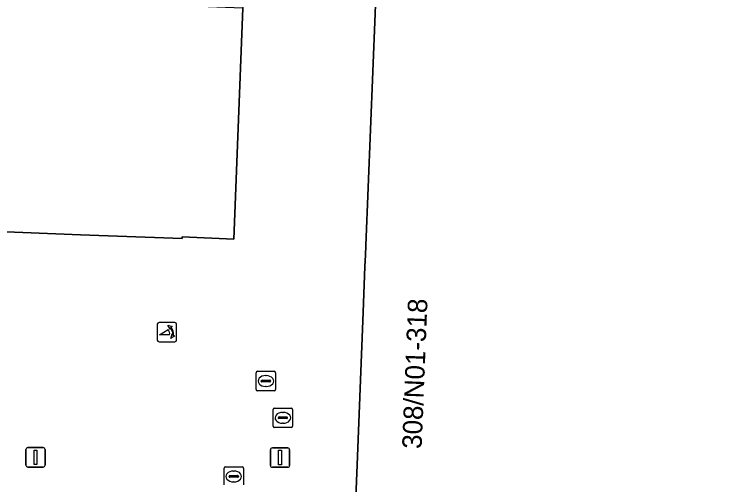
# Model space of a CAD drawing. Extents: x 160888 to 161385, y 386490 to 386908.
# Drawn here: x 161269.97 to 161306.64, y 386804.6 to 386828.79 of the extents above; entities that cross this region are included whole.
import ezdxf

# ---------------------------------------------------------------- set-up
doc = ezdxf.new("R2010")
doc.units = 0
for name, color, linetype in [('IMGEO_Kolk', 7, 'Continuous'), ('IMGEO_Lichtmast', 7, 'Continuous'), ('IMGEO_Pand', 7, 'Continuous'), ('IMGEO_Pand_nummerreeks', 7, 'Continuous'), ('IMGEO_Poller', 7, 'Continuous'), ('IMGEO_Rioolput', 7, 'Continuous'), ('IMGEO_Voetgangersgebied_open', 7, 'Continuous')]:
    doc.layers.add(name, color=color, linetype=linetype)

msp = doc.modelspace()

# ---------------------------------------------------------------- linework, layer by layer
at = {"layer": 'IMGEO_Kolk'}
for p, q in [((161280.752, 386804.599), (161280.752, 386805.451)), ((161280.827, 386805.525), (161281.679, 386805.525)), ((161281.753, 386805.451), (161281.753, 386804.599)), ((161281.054, 386805.068), (161281.452, 386805.068)), ((161281.24, 386805.305), (161281.265, 386805.305)), ((161281.011, 386805.019), (161281.011, 386805.031)), ((161281.449, 386804.982), (161281.051, 386804.982)), ((161281.263, 386804.745), (161281.238, 386804.745)), ((161281.495, 386805.031), (161281.495, 386805.019))]:
    msp.add_line(p, q, dxfattribs=at)
for points in [[(161280.752, 386804.599), (161280.752, 386805.451)], [(161280.827, 386805.525), (161281.679, 386805.525)], [(161281.753, 386805.451), (161281.753, 386804.599)]]:
    msp.add_lwpolyline(points, dxfattribs=at)
for centre, radius, start, end in [((161280.829, 386805.449), 0.0765, 91.552, 178.448), ((161280.829, 386805.449), 0.0765, 91.552, 178.448), ((161281.677, 386805.449), 0.0765, 1.552, 88.448), ((161281.677, 386805.449), 0.0765, 1.552, 88.448), ((161281.051, 386805.028), 0.0403, 85.8775, 175.7526), ((161281.456, 386805.03), 0.0386, 1.7309, 96.639), ((161281.048, 386805.018), 0.0366, 178.938, 274.7102), ((161281.452, 386805.025), 0.043, 264.8664, 352.4533)]:
    msp.add_arc(centre, radius, start, end, dxfattribs=at)
for centre, major_axis, ratio, start_param, end_param in [((161281.239, 386805.025), (-0.387, 0.002), 0.722429, 4.712389, 7.853982), ((161281.264, 386805.025), (-0.39, 0.002), 0.717154, 1.570796, 4.712389)]:
    msp.add_ellipse(centre, major_axis=major_axis, ratio=ratio, start_param=start_param, end_param=end_param, dxfattribs=at)
at = {"layer": 'IMGEO_Lichtmast'}
for p, q in [((161270.566, 386805.609), (161270.566, 386806.409)), ((161270.566, 386806.409), (161270.566, 386805.609)), ((161270.666, 386806.509), (161271.456, 386806.509)), ((161271.456, 386806.509), (161270.666, 386806.509)), ((161271.556, 386806.409), (161271.556, 386805.609)), ((161271.556, 386805.609), (161271.556, 386806.409)), ((161283.136, 386805.594), (161283.136, 386806.394)), ((161283.136, 386806.394), (161283.136, 386805.594)), ((161283.236, 386806.494), (161284.026, 386806.494)), ((161284.026, 386806.494), (161283.236, 386806.494)), ((161284.126, 386806.394), (161284.126, 386805.594)), ((161284.126, 386805.594), (161284.126, 386806.394)), ((161271.456, 386805.509), (161270.666, 386805.509)), ((161270.666, 386805.509), (161271.456, 386805.509)), ((161284.026, 386805.494), (161283.236, 386805.494)), ((161283.236, 386805.494), (161284.026, 386805.494))]:
    msp.add_line(p, q, dxfattribs=at)
for points in [[(161270.986, 386806.384), (161271.136, 386806.384), (161271.136, 386805.634), (161270.986, 386805.634), (161270.986, 386806.384)], [(161283.556, 386806.369), (161283.706, 386806.369), (161283.706, 386805.619), (161283.556, 386805.619), (161283.556, 386806.369)]]:
    msp.add_lwpolyline(points, dxfattribs=at)
for centre, start, end in [((161270.666, 386806.409), 90, 180), ((161270.666, 386806.409), 90, 180), ((161271.456, 386806.409), 0, 90), ((161271.456, 386806.409), 360, 90), ((161283.236, 386806.394), 90, 180), ((161283.236, 386806.394), 90, 180), ((161284.026, 386806.394), 0, 90), ((161284.026, 386806.394), 360, 90), ((161270.666, 386805.609), 180, 270), ((161270.666, 386805.609), 180, 270), ((161271.456, 386805.609), 270, 0), ((161271.456, 386805.609), 270, 0), ((161283.236, 386805.594), 180, 270), ((161283.236, 386805.594), 180, 270), ((161284.026, 386805.594), 270, 0), ((161284.026, 386805.594), 270, 0)]:
    msp.add_arc(centre, 0.1, start, end, dxfattribs=at)
at = {"layer": 'IMGEO_Pand'}
for points in [[(161331.47, 386815.113), (161335.837, 386814.939), (161336.142, 386822.581), (161336.697, 386836.512), (161288.895, 386838.421), (161288.608, 386831.222), (161288.513, 386828.834), (161288.037, 386816.903), (161288.017, 386816.411), (161287.994, 386815.819), (161287.9, 386813.473), (161287.589, 386805.614), (161287.138, 386794.242), (161286.896, 386788.152), (161286.841, 386786.774), (161286.811, 386786.009), (161327.555, 386784.385), (161330.241, 386784.278)], [(161281.723, 386829.096), (161269.188, 386829.608), (161259.736, 386829.994), (161252.467, 386830.291), (161238.036, 386830.88), (161223.504, 386831.473), (161216.339, 386831.766), (161201.804, 386832.359), (161201.32, 386820.359), (161215.857, 386819.772), (161223.022, 386819.483), (161237.554, 386818.897), (161251.986, 386818.314), (161259.254, 386818.021), (161268.706, 386817.64), (161273.381, 386817.451), (161278.601, 386817.252), (161278.605, 386817.352), (161281.256, 386817.22)]]:
    msp.add_lwpolyline(points, close=True, dxfattribs=at)
at = {"layer": 'IMGEO_Poller'}
for p, q in [((161277.321, 386812.847), (161277.321, 386812.04)), ((161277.321, 386812.847), (161277.321, 386812.04)), ((161278.223, 386812.942), (161277.415, 386812.942)), ((161278.223, 386812.942), (161277.415, 386812.942)), ((161278.317, 386812.04), (161278.317, 386812.847)), ((161278.317, 386812.04), (161278.317, 386812.847)), ((161277.415, 386811.945), (161278.223, 386811.945)), ((161277.415, 386811.945), (161278.223, 386811.945))]:
    msp.add_line(p, q, dxfattribs=at)
for points in [[(161278, 386812.671), (161277.988, 386812.598), (161277.863, 386812.803)], [(161277.863, 386812.803), (161278.094, 386812.737), (161278.023, 386812.705)], [(161277.956, 386812.298), (161277.443, 386812.298), (161277.873, 386812.573)], [(161278.016, 386812.126), (161278.082, 386812.357), (161278.112, 386812.289)], [(161278.148, 386812.262), (161278.22, 386812.251), (161278.016, 386812.126)]]:
    msp.add_lwpolyline(points, dxfattribs=at)
for centre, radius, start, end in [((161277.415, 386812.847), 0.0946, 90, 180), ((161277.415, 386812.847), 0.0946, 90, 180), ((161278.223, 386812.847), 0.0946, 0, 90), ((161278.223, 386812.847), 0.0946, 0, 90), ((161277.628, 386812.348), 0.332, 351.3247, 42.4854), ((161277.642, 386812.358), 0.476, 351.7527, 41.1691), ((161277.642, 386812.358), 0.516, 349.3569, 42.2912), ((161277.415, 386812.04), 0.0946, 180, 270), ((161277.415, 386812.04), 0.0946, 180, 270), ((161278.223, 386812.04), 0.0946, 270, 0), ((161278.223, 386812.04), 0.0946, 270, 0)]:
    msp.add_arc(centre, radius, start, end, dxfattribs=at)
at = {"layer": 'IMGEO_Rioolput'}
for p, q in [((161282.404, 386809.504), (161282.404, 386810.356)), ((161282.479, 386810.43), (161283.331, 386810.43)), ((161282.892, 386810.21), (161282.917, 386810.21)), ((161283.405, 386810.356), (161283.405, 386809.504)), ((161282.663, 386809.924), (161282.663, 386809.936)), ((161283.101, 386809.887), (161282.703, 386809.887)), ((161282.706, 386809.973), (161283.104, 386809.973)), ((161283.147, 386809.936), (161283.147, 386809.924)), ((161282.915, 386809.65), (161282.89, 386809.65)), ((161283.331, 386809.43), (161282.479, 386809.43)), ((161283.277, 386807.613), (161283.277, 386808.465)), ((161283.352, 386808.539), (161284.204, 386808.539)), ((161284.278, 386808.465), (161284.278, 386807.613)), ((161283.536, 386808.033), (161283.536, 386808.045)), ((161283.579, 386808.082), (161283.977, 386808.082)), ((161283.765, 386808.319), (161283.79, 386808.319)), ((161284.02, 386808.045), (161284.02, 386808.033)), ((161283.974, 386807.996), (161283.576, 386807.996)), ((161283.788, 386807.759), (161283.763, 386807.759)), ((161284.204, 386807.539), (161283.352, 386807.539))]:
    msp.add_line(p, q, dxfattribs=at)
for points in [[(161282.404, 386809.504), (161282.404, 386810.356)], [(161282.479, 386810.43), (161283.331, 386810.43)], [(161283.405, 386810.356), (161283.405, 386809.504)], [(161283.331, 386809.43), (161282.479, 386809.43)], [(161283.277, 386807.613), (161283.277, 386808.465)], [(161283.352, 386808.539), (161284.204, 386808.539)], [(161284.278, 386808.465), (161284.278, 386807.613)], [(161284.204, 386807.539), (161283.352, 386807.539)]]:
    msp.add_lwpolyline(points, dxfattribs=at)
for centre, radius, start, end in [((161282.481, 386810.354), 0.0765, 91.552, 178.448), ((161282.481, 386810.354), 0.0765, 91.552, 178.448), ((161283.329, 386810.354), 0.0765, 1.552, 88.448), ((161283.329, 386810.354), 0.0765, 1.552, 88.448), ((161282.703, 386809.933), 0.0403, 85.8775, 175.7526), ((161282.7, 386809.923), 0.0366, 178.938, 274.7102), ((161283.104, 386809.93), 0.043, 264.8664, 352.4533), ((161283.108, 386809.935), 0.0386, 1.7309, 96.639), ((161282.481, 386809.506), 0.0765, 181.552, 268.448), ((161282.481, 386809.506), 0.0765, 181.552, 268.448), ((161283.329, 386809.506), 0.0765, 271.552, 358.448), ((161283.329, 386809.506), 0.0765, 271.552, 358.448), ((161283.354, 386808.463), 0.0765, 91.552, 178.448), ((161283.354, 386808.463), 0.0765, 91.552, 178.448), ((161284.202, 386808.463), 0.0765, 1.552, 88.448), ((161284.202, 386808.463), 0.0765, 1.552, 88.448), ((161283.576, 386808.042), 0.0403, 85.8775, 175.7526), ((161283.573, 386808.032), 0.0366, 178.938, 274.7102), ((161283.977, 386808.039), 0.043, 264.8664, 352.4533), ((161283.981, 386808.044), 0.0386, 1.7309, 96.639), ((161283.354, 386807.615), 0.0765, 181.552, 268.448), ((161283.354, 386807.615), 0.0765, 181.552, 268.448), ((161284.202, 386807.615), 0.0765, 271.552, 358.448), ((161284.202, 386807.615), 0.0765, 271.552, 358.448)]:
    msp.add_arc(centre, radius, start, end, dxfattribs=at)
for centre, major_axis, ratio, start_param, end_param in [((161282.891, 386809.93), (-0.387, 0.002), 0.722429, 4.712389, 7.853982), ((161282.916, 386809.93), (-0.39, 0.002), 0.717154, 1.570796, 4.712389), ((161283.764, 386808.039), (-0.387, 0.002), 0.722429, 4.712389, 7.853982), ((161283.789, 386808.039), (-0.39, 0.002), 0.717154, 1.570796, 4.712389)]:
    msp.add_ellipse(centre, major_axis=major_axis, ratio=ratio, start_param=start_param, end_param=end_param, dxfattribs=at)
at = {"layer": 'IMGEO_Voetgangersgebied_open'}
msp.add_lwpolyline([(161267.255, 386787.478), (161286.841, 386786.774), (161286.896, 386788.152), (161287.138, 386794.242), (161287.589, 386805.614), (161287.9, 386813.473), (161287.994, 386815.819), (161288.017, 386816.411), (161288.037, 386816.903), (161288.513, 386828.834), (161288.608, 386831.222), (161288.895, 386838.421), (161282.13, 386838.652), (161282.087, 386837.641), (161281.825, 386831.496), (161281.723, 386829.096), (161281.256, 386817.22), (161278.605, 386817.352), (161278.601, 386817.252), (161273.381, 386817.451), (161268.706, 386817.64)], dxfattribs=at)

# ---------------------------------------------------------------- texts
at = {"layer": 'IMGEO_Pand_nummerreeks'}
msp.add_text('308/N01-318', height=1, rotation=87.7256, dxfattribs=at).set_placement((161290.906, 386806.426))

doc.saveas('drawing.dxf')
